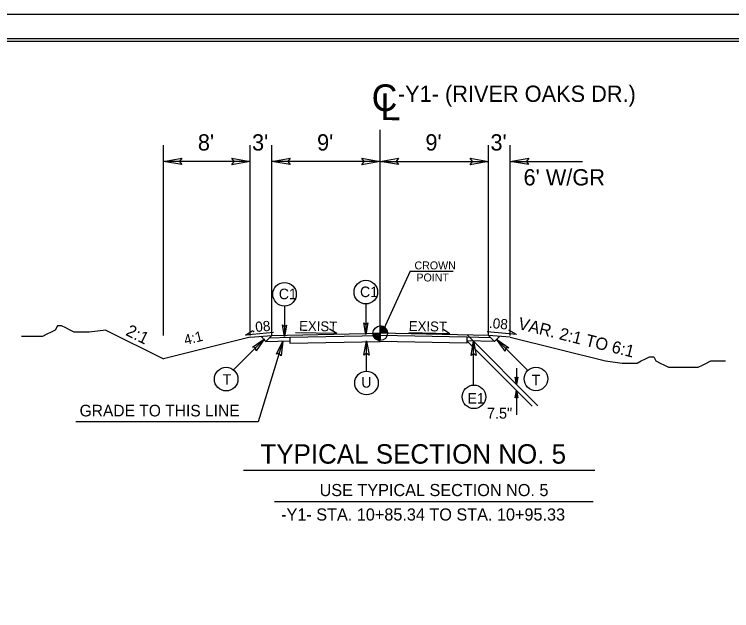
# Model space of a CAD drawing. Extents: x 1818040 to 1825768, y 638918 to 648046.
# Drawn here: x 1821216 to 1821878, y 643153 to 643703 of the extents above; entities that cross this region are included whole.
import ezdxf

# ---------------------------------------------------------------- set-up
doc = ezdxf.new("R2010")
doc.units = 0
for name, color, linetype in [('Old_Level_1', 7, 'Continuous'), ('Prop Dimension', 7, 'Continuous'), ('Prop Dimension Text', 7, 'Continuous'), ('Sheet Plot Border Inside CELL', 7, 'Continuous'), ('Sheet Plot Border Outside CELL', 7, 'Continuous'), ('Sheet Typical CELL', 7, 'Continuous'), ('Typical Grade Point Symbol CELL', 7, 'Continuous'), ('Typical ID Circle CELL', 7, 'Continuous'), ('Typical Pavement Slope CELL', 7, 'Continuous'), ('Typical Pavement Slope Information CELL', 7, 'Continuous'), ('Typical Shoulder Slope CELL', 7, 'Continuous'), ('Typical Slope Point Local CELL', 7, 'Continuous'), ('Typical Terminator CELL', 7, 'Continuous'), ('Typical Text Centerline CELL', 7, 'Continuous'), ('Typical Text General CELL', 7, 'Continuous'), ('Typical Text Grade Point CELL', 7, 'Continuous'), ('Typical Text ID Circle CELL', 7, 'Continuous'), ('Typical Text Label CELL', 7, 'Continuous')]:
    doc.layers.add(name, color=color, linetype=linetype)

msp = doc.modelspace()

# ---------------------------------------------------------------- linework, layer by layer
at = {"layer": 'Old_Level_1'}
for p, q in [((1821353.38, 643407.19), (1821353.38, 643582.64)), ((1821447.85, 643401.66), (1821443.17, 643406.34)), ((1821453.38, 643407.19), (1821447.85, 643401.66)), ((1821451.25, 643405.06), (1821469.86, 643405.43)), ((1821469.86, 643405.43), (1821553.38, 643407.1)), ((1821469.86, 643405.43), (1821469.86, 643400.01)), ((1821633.34, 643405.5), (1821553.38, 643407.1)), ((1821655.5, 643405.06), (1821633.34, 643405.5)), ((1821633.34, 643405.5), (1821633.34, 643400.08)), ((1821633.78, 643407.37), (1821698.94, 643342.21)), ((1821653.38, 643407.19), (1821658.91, 643401.66)), ((1821658.91, 643401.66), (1821663.58, 643406.34)), ((1821463.58, 643401.99), (1821440.78, 643327.44)), ((1821447.85, 643401.66), (1821469.86, 643402.1)), ((1821469.86, 643400.01), (1821553.38, 643401.68)), ((1821633.34, 643400.08), (1821553.38, 643401.68)), ((1821633.34, 643402.17), (1821693.46, 643342.05)), ((1821658.91, 643401.66), (1821633.34, 643402.17)), ((1821679.1, 643376.88), (1821679.1, 643362.05)), ((1821679.11, 643356.28), (1821679.11, 643333.96)), ((1821440.78, 643327.44), (1821272.37, 643327.44))]:
    msp.add_line(p, q, dxfattribs=at)
at = {"layer": 'Prop Dimension'}
for p, q in [((1821553.38, 643409.19), (1821553.38, 643596.84)), ((1821433.38, 643407.19), (1821433.38, 643582.64)), ((1821453.38, 643407.19), (1821453.38, 643582.64)), ((1821653.38, 643407.19), (1821653.38, 643582.64)), ((1821673.38, 643407.19), (1821673.38, 643582.64)), ((1821433.38, 643567.64), (1821353.38, 643567.64)), ((1821553.38, 643567.64), (1821453.38, 643567.64)), ((1821553.38, 643567.64), (1821653.38, 643567.64)), ((1821673.38, 643567.64), (1821739.91, 643567.64))]:
    msp.add_line(p, q, dxfattribs=at)
at = {"layer": 'Sheet Plot Border Inside CELL'}
msp.add_lwpolyline([(1822095.84, 643680.85), (1820429.34, 643680.85), (1820429.34, 642625.75), (1822095.84, 642625.75)], close=True, dxfattribs=at)
at = {"layer": 'Sheet Plot Border Outside CELL'}
msp.add_lwpolyline([(1822100.34, 643703.3), (1820416.34, 643703.3), (1820416.34, 642603.3), (1822100.34, 642603.3)], close=True, dxfattribs=at)
at = {"layer": 'Sheet Typical CELL'}
msp.add_line((1822100.34, 643703.3), (1820416.34, 643703.3), dxfattribs=at)
msp.add_lwpolyline([(1822083.34, 643678.3), (1820583.34, 643678.3), (1820583.34, 642628.3), (1822083.34, 642628.3)], close=True, dxfattribs=at)
at = {"layer": 'Typical Grade Point Symbol CELL'}
for p, q in [((1821553.38, 643409.19), (1821553.38, 643415.9)), ((1821546.66, 643409.19), (1821553.38, 643409.19)), ((1821553.36, 643402.47), (1821553.38, 643409.19)), ((1821553.38, 643409.19), (1821553.36, 643402.47)), ((1821560.09, 643409.19), (1821553.38, 643409.19))]:
    msp.add_line(p, q, dxfattribs=at)
for points in [[(1821553.44, 643415.9), (1821553.44, 643415.9), (1821553.44, 643409.19)], [(1821553.57, 643415.9), (1821553.57, 643409.19)], [(1821553.71, 643415.89), (1821553.71, 643409.19)], [(1821553.84, 643415.89), (1821553.84, 643409.19)], [(1821553.97, 643415.87), (1821553.97, 643409.19)], [(1821554.11, 643415.86), (1821554.11, 643409.19)], [(1821554.24, 643415.84), (1821554.24, 643409.19)], [(1821554.38, 643415.83), (1821554.38, 643409.19)], [(1821554.51, 643415.81), (1821554.51, 643409.19)], [(1821554.65, 643415.78), (1821554.65, 643409.19)], [(1821554.78, 643415.75), (1821554.78, 643409.19)], [(1821554.92, 643415.72), (1821554.92, 643409.19)], [(1821555.05, 643415.69), (1821555.05, 643409.19)], [(1821555.18, 643415.65), (1821555.18, 643409.19)], [(1821555.32, 643415.62), (1821555.32, 643409.19)], [(1821555.45, 643415.57), (1821555.45, 643409.19)], [(1821555.59, 643415.53), (1821555.59, 643409.19)], [(1821555.72, 643415.48), (1821555.72, 643409.19)], [(1821555.85, 643415.42), (1821555.85, 643409.19)], [(1821555.99, 643415.36), (1821555.99, 643409.19)], [(1821556.12, 643415.3), (1821556.12, 643409.19)], [(1821556.26, 643415.24), (1821556.26, 643409.19)], [(1821556.39, 643415.19), (1821556.39, 643409.19)], [(1821556.53, 643415.11), (1821556.53, 643409.19)], [(1821556.66, 643415.04), (1821556.66, 643409.19)], [(1821556.79, 643414.96), (1821556.79, 643409.19)], [(1821556.93, 643414.89), (1821556.93, 643409.19)], [(1821557.06, 643414.8), (1821557.06, 643409.19)], [(1821557.2, 643414.71), (1821557.2, 643409.19)], [(1821557.33, 643414.6), (1821557.33, 643409.19)], [(1821557.47, 643414.51), (1821557.47, 643409.19)], [(1821557.6, 643414.41), (1821557.6, 643409.19)], [(1821557.74, 643414.29), (1821557.74, 643409.19)], [(1821557.87, 643414.17), (1821557.87, 643409.19)], [(1821558, 643414.05), (1821558, 643409.19)], [(1821558.14, 643413.92), (1821558.14, 643409.19)], [(1821558.27, 643413.78), (1821558.27, 643409.19)], [(1821558.41, 643413.63), (1821558.41, 643409.19)], [(1821558.54, 643413.47), (1821558.54, 643409.19)], [(1821558.67, 643413.31), (1821558.67, 643409.19)], [(1821558.81, 643413.13), (1821558.81, 643409.19)], [(1821558.94, 643412.93), (1821558.94, 643409.19)], [(1821559.08, 643412.72), (1821559.08, 643409.19)], [(1821559.21, 643412.5), (1821559.21, 643409.19)], [(1821559.35, 643412.26), (1821559.35, 643409.19)], [(1821559.48, 643411.98), (1821559.48, 643409.19)], [(1821559.61, 643411.66), (1821559.61, 643409.19)], [(1821559.75, 643411.29), (1821559.75, 643409.19)], [(1821559.88, 643410.83), (1821559.88, 643409.19)], [(1821560.02, 643410.14), (1821560.02, 643409.19)], [(1821546.69, 643409.19), (1821546.69, 643408.46)], [(1821546.83, 643409.19), (1821546.83, 643407.67)], [(1821546.96, 643409.19), (1821546.96, 643407.19)], [(1821547.1, 643409.19), (1821547.1, 643406.79)], [(1821547.23, 643409.19), (1821547.23, 643406.47)], [(1821547.37, 643409.19), (1821547.37, 643406.19)], [(1821547.5, 643409.19), (1821547.5, 643405.94)], [(1821547.63, 643409.19), (1821547.63, 643405.7)], [(1821547.77, 643409.19), (1821547.77, 643405.49)], [(1821547.9, 643409.19), (1821547.9, 643405.29)], [(1821548.04, 643409.19), (1821548.04, 643405.11)], [(1821548.17, 643409.19), (1821548.17, 643404.95)], [(1821548.31, 643409.19), (1821548.31, 643404.79)], [(1821548.44, 643409.19), (1821548.44, 643404.64)], [(1821548.57, 643409.19), (1821548.57, 643404.49)], [(1821548.71, 643409.19), (1821548.71, 643404.35)], [(1821548.84, 643409.19), (1821548.84, 643404.23)], [(1821548.98, 643409.19), (1821548.98, 643404.11)], [(1821549.11, 643409.19), (1821549.11, 643404)], [(1821549.25, 643409.19), (1821549.25, 643403.89)], [(1821549.38, 643409.19), (1821549.38, 643403.79)], [(1821549.51, 643409.19), (1821549.51, 643403.7)], [(1821549.65, 643409.19), (1821549.65, 643403.61)], [(1821549.78, 643409.19), (1821549.78, 643403.52)], [(1821549.92, 643409.19), (1821549.92, 643403.43)], [(1821550.05, 643409.19), (1821550.05, 643403.35)], [(1821550.19, 643409.19), (1821550.19, 643403.28)], [(1821550.32, 643409.19), (1821550.32, 643403.2)], [(1821550.45, 643409.19), (1821550.45, 643403.15)], [(1821550.59, 643409.19), (1821550.59, 643403.08)], [(1821550.72, 643409.19), (1821550.72, 643403.03)], [(1821550.86, 643409.19), (1821550.86, 643402.97)], [(1821550.99, 643409.19), (1821550.99, 643402.91)], [(1821551.13, 643409.19), (1821551.13, 643402.86)], [(1821551.26, 643409.19), (1821551.26, 643402.82)], [(1821551.39, 643409.19), (1821551.39, 643402.77)], [(1821551.53, 643409.19), (1821551.53, 643402.74)], [(1821551.66, 643409.19), (1821551.66, 643402.7)], [(1821551.8, 643409.19), (1821551.8, 643402.67)], [(1821551.93, 643409.19), (1821551.93, 643402.64)], [(1821552.07, 643409.19), (1821552.07, 643402.61)], [(1821552.2, 643409.19), (1821552.2, 643402.58)], [(1821552.33, 643409.19), (1821552.33, 643402.56)], [(1821552.47, 643409.19), (1821552.47, 643402.53)], [(1821552.6, 643409.19), (1821552.6, 643402.52)], [(1821552.74, 643409.19), (1821552.74, 643402.5)], [(1821552.87, 643409.19), (1821552.87, 643402.49)], [(1821553.01, 643409.19), (1821553.01, 643402.49)], [(1821553.14, 643409.19), (1821553.14, 643402.47)], [(1821553.27, 643409.19), (1821553.27, 643402.47), (1821553.27, 643402.47)]]:
    msp.add_lwpolyline(points, dxfattribs=at)
msp.add_circle((1821553.37, 643409.19), 6.71, dxfattribs=at)
for start, end in [(359.99048, 89.99048), (179.99048, 269.99048)]:
    msp.add_arc((1821553.37, 643409.19), 6.71, start, end, dxfattribs=at)
at = {"layer": 'Typical ID Circle CELL'}
for p, q in [((1821540.06, 643436.22), (1821540.06, 643408.11)), ((1821465.06, 643434.28), (1821465.06, 643406.17)), ((1821417.87, 643375.43), (1821446.59, 643404.13)), ((1821689.53, 643374.87), (1821660.79, 643403.59)), ((1821540.68, 643374.2), (1821540.68, 643402.31)), ((1821639.58, 643361.37), (1821639.58, 643399.21))]:
    msp.add_line(p, q, dxfattribs=at)
for centre in [(1821465.06, 643445.15), (1821540.06, 643447.09), (1821411.18, 643366.85), (1821697.08, 643367.04), (1821540.68, 643363.33), (1821639.85, 643350.5)]:
    msp.add_circle(centre, 10.88, dxfattribs=at)
at = {"layer": 'Typical Pavement Slope CELL'}
for p in [(1821453.38, 643407.19), (1821653.38, 643407.19)]:
    msp.add_line(p, (1821553.38, 643409.19), dxfattribs=at)
at = {"layer": 'Typical Pavement Slope Information CELL'}
for p, q in [((1821429.05, 643407.49), (1821435.94, 643411.66)), ((1821454.88, 643409.98), (1821429.05, 643407.49)), ((1821513.18, 643408.89), (1821475.21, 643409.65)), ((1821513.18, 643408.89), (1821506.42, 643412.97)), ((1821617.74, 643408.72), (1821579.77, 643409.48)), ((1821617.74, 643408.72), (1821610.99, 643412.8)), ((1821679, 643407.96), (1821652.12, 643410.56)), ((1821679, 643407.96), (1821672.11, 643412.13))]:
    msp.add_line(p, q, dxfattribs=at)
at = {"layer": 'Typical Shoulder Slope CELL'}
for p, q in [((1821433.38, 643405.52), (1821453.38, 643407.19)), ((1821673.38, 643405.52), (1821653.38, 643407.19))]:
    msp.add_line(p, q, dxfattribs=at)
at = {"layer": 'Typical Slope Point Local CELL'}
for p, q in [((1821300.18, 643412.12), (1821353.38, 643385.52)), ((1821433.38, 643405.52), (1821353.38, 643385.52)), ((1821673.38, 643405.52), (1821761.13, 643383.58))]:
    msp.add_line(p, q, dxfattribs=at)
for points in [[(1821300.18, 643412.12), (1821284.62, 643410.18), (1821280.73, 643410.18), (1821274.89, 643410.18), (1821271, 643410.18), (1821267.11, 643412.12), (1821263.22, 643414.07), (1821259.33, 643416.03), (1821255.44, 643416.03), (1821253.48, 643412.12), (1821249.59, 643410.18), (1821245.7, 643408.23), (1821241.81, 643406.29), (1821237.92, 643406.29), (1821234.03, 643406.29), (1821230.14, 643406.29), (1821226.25, 643406.29), (1821222.36, 643406.29)], [(1821761.13, 643383.58), (1821776.69, 643381.65), (1821780.58, 643381.65), (1821786.42, 643381.65), (1821790.31, 643381.65), (1821794.2, 643383.58), (1821798.09, 643385.54), (1821801.98, 643387.49), (1821805.87, 643387.49), (1821807.82, 643383.58), (1821811.71, 643381.65), (1821815.6, 643379.69), (1821819.49, 643377.76), (1821823.38, 643377.76), (1821827.27, 643377.76), (1821831.16, 643377.76), (1821835.05, 643377.76), (1821838.94, 643377.76), (1821842.83, 643377.76), (1821846.72, 643377.76), (1821850.61, 643379.69), (1821854.5, 643381.65), (1821858.39, 643383.58), (1821864.24, 643383.58), (1821868.13, 643383.58), (1821872.02, 643383.58)]]:
    msp.add_lwpolyline(points, dxfattribs=at)
at = {"layer": 'Typical Terminator CELL'}
for points in [[(1821370.25, 643564.73), (1821353.38, 643567.64), (1821370.35, 643570.64), (1821368.19, 643567.64)], [(1821416.5, 643570.54), (1821433.38, 643567.64), (1821416.41, 643564.64), (1821418.57, 643567.64)], [(1821470.25, 643564.73), (1821453.38, 643567.64), (1821470.35, 643570.64), (1821468.19, 643567.64)], [(1821536.5, 643570.54), (1821553.38, 643567.64), (1821536.41, 643564.64), (1821538.57, 643567.64)], [(1821570.25, 643564.73), (1821553.38, 643567.64), (1821570.35, 643570.64), (1821568.19, 643567.64)], [(1821636.5, 643570.54), (1821653.38, 643567.64), (1821636.41, 643564.64), (1821638.57, 643567.64)], [(1821690.25, 643564.73), (1821673.38, 643567.64), (1821690.35, 643570.64), (1821688.19, 643567.64)], [(1821466.88, 643416.71), (1821465.06, 643406.17), (1821463.19, 643416.77), (1821465.06, 643415.43)], [(1821541.88, 643418.65), (1821540.06, 643408.11), (1821538.19, 643418.71), (1821540.06, 643417.36)], [(1821435.52, 643396.32), (1821446.59, 643404.13), (1821438.77, 643392.96), (1821438.3, 643395.84)], [(1821668.61, 643392.52), (1821660.79, 643403.59), (1821671.97, 643395.78), (1821669.09, 643395.31)], [(1821457.52, 643389.85), (1821463.59, 643401.97), (1821461.98, 643388.43), (1821460.2, 643390.75)], [(1821538.38, 643388.95), (1821540.68, 643402.31), (1821543.05, 643388.88), (1821540.68, 643390.59)], [(1821637.28, 643388.69), (1821639.58, 643402.05), (1821641.95, 643388.61), (1821639.58, 643390.32)], [(1821680.31, 643368.72), (1821679.1, 643362.05), (1821677.97, 643368.77), (1821679.15, 643367.91)], [(1821677.98, 643349.59), (1821679.11, 643356.28), (1821680.32, 643349.57), (1821679.13, 643350.41)]]:
    msp.add_lwpolyline(points, close=True, dxfattribs=at)
at = {"layer": 'Typical Text Grade Point CELL'}
for q in [(1821554.92, 643409.19), (1821620.69, 643466.29)]:
    msp.add_line((1821580.89, 643466.29), q, dxfattribs=at)
at = {"layer": 'Typical Text Label CELL'}
for p, q in [((1821427.18, 643282.89), (1821751.25, 643282.89)), ((1821455.87, 643254.04), (1821749.71, 643254.04))]:
    msp.add_line(p, q, dxfattribs=at)

# ---------------------------------------------------------------- texts
at = {"layer": 'Prop Dimension Text'}
for s, height, p in [('-Y1- (RIVER OAKS DR.)', 15, (1821569.64, 643622.58)), ("8'", 15, (1821385.07, 643577.7)), ("3'", 15, (1821435.07, 643577.7)), ("9'", 15, (1821495.07, 643577.7)), ("9'", 15, (1821595.07, 643577.7)), ("3'", 15, (1821655.07, 643577.7)), ("6' W/GR", 15, (1821685.59, 643545.49)), ('7.5"', 10, (1821651.8, 643330.43))]:
    msp.add_text(s, height=height, dxfattribs=at).set_placement(p)
at = {"layer": 'Typical Pavement Slope Information CELL'}
for s, p in [('EXIST', (1821478.42, 643411.47)), ('EXIST ', (1821579.63, 643411.34))]:
    msp.add_text(s, height=9.107, rotation=358.85426, dxfattribs=at).set_placement(p)
at = {"layer": 'Typical Slope Point Local CELL'}
for s, rotation, p in [('.08', 355.23853, (1821653.38, 643414.07)), ('.08', 4.76147, (1821434.97, 643409.99)), ('4:1', 14.03624, (1821373.54, 643398.21))]:
    msp.add_text(s, height=9.373, rotation=rotation, dxfattribs=at).set_placement(p)
at = {"layer": 'Typical Text Centerline CELL'}
msp.add_text('C', height=24.6, dxfattribs=at).set_placement((1821545.44, 643614.11))
msp.add_text('L', height=24.62, rotation=359.9469, dxfattribs=at).set_placement((1821553.62, 643605.71))
at = {"layer": 'Typical Text General CELL'}
for s, height, rotation, p in [('VAR. 2:1 TO 6:1', 11.1896, 345.96376, (1821679.82, 643413.23)), ('2:1 ', 11.19, 333.43495, (1821317.71, 643407.78))]:
    msp.add_text(s, height=height, rotation=rotation, dxfattribs=at).set_placement(p)
msp.add_text('GRADE TO THIS LINE', height=10.742, dxfattribs=at).set_placement((1821275.95, 643332.44))
at = {"layer": 'Typical Text Grade Point CELL'}
for s, height, p in [('CROWN', 7.34, (1821584.98, 643468.05)), ('POINT', 7.34, (1821586.75, 643456.92)), ('-Y1- STA. 10+85.34 TO STA. 10+95.33', 11.1896, (1821461.91, 643236.42))]:
    msp.add_text(s, height=height, dxfattribs=at).set_placement(p)
at = {"layer": 'Typical Text ID Circle CELL'}
for s, height, p in [('C1', 9.735, (1821459.74, 643440.55)), ('C1', 9.735, (1821534.74, 643442.49)), ('T', 9.73, (1821407.87, 643361.63)), ('T', 9.73, (1821693.14, 643361.09)), ('U', 9.73, (1821535.92, 643359.02)), ('E1', 9.735, (1821633.89, 643344.27))]:
    msp.add_text(s, height=height, dxfattribs=at).set_placement(p)
at = {"layer": 'Typical Text Label CELL'}
for s, height, p in [('TYPICAL SECTION NO. 5  ', 17.9034, (1821442.81, 643288.89)), ('USE TYPICAL SECTION NO. 5', 11.1896, (1821497.4, 643258.94))]:
    msp.add_text(s, height=height, dxfattribs=at).set_placement(p)

doc.saveas('drawing.dxf')
